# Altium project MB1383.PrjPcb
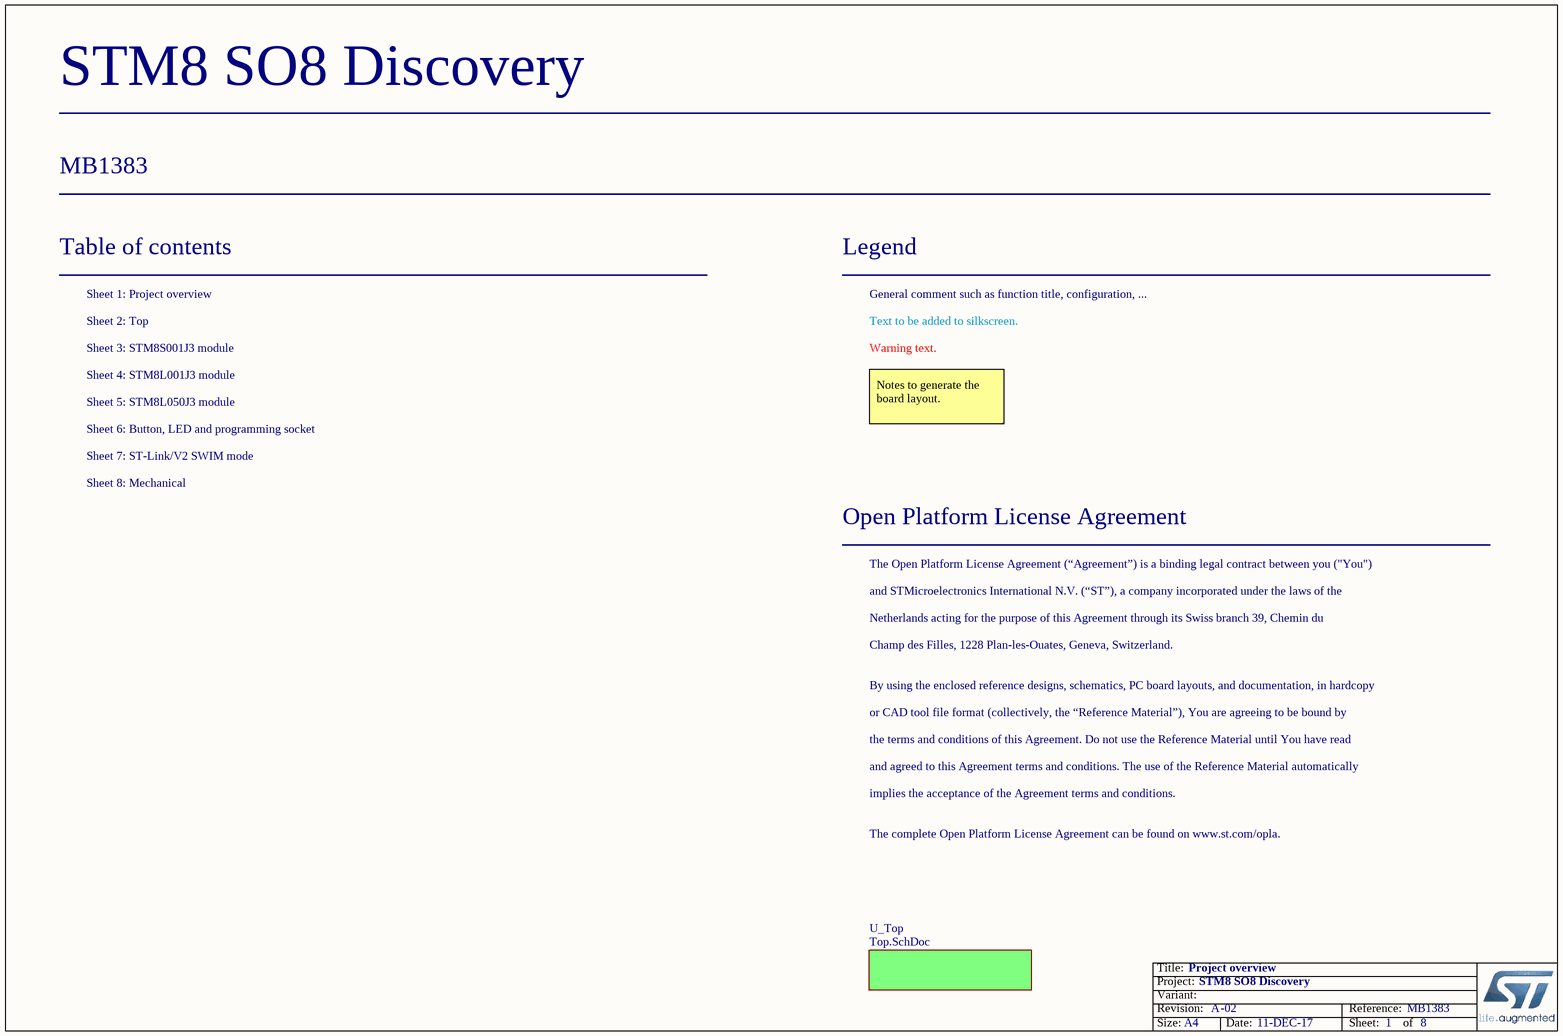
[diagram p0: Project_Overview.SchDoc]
Board_Assembly_Revision: 02; Board_Document_Date: 11-DEC-17; Board_Name: STM8 SO8 Discovery; Board_PCB_Revision: A; Board_Reference: MB1383
8 sheets, 85 parts. Net scope: flat (ports and power ports of the same name join across sheets).
Board file: MB1383.PcbDoc
Sheets:
  Project_Overview.SchDoc
    U_Top = Top.SchDoc
      U_ST-LinkV2_SWIM = ST-LinkV2_SWIM.SchDoc
      U_Mechanical = Mechanical.SchDoc
      U_Button-Led-ProgSocket = Button-Led-ProgSocket.SchDoc
      U_STM8L001J3_Module = STM8L001J3_Module.SchDoc
      U_STM8S001J3_Module = STM8S001J3_Module.SchDoc
      U_STM8L050J3_Module = STM8L050J3_Module.SchDoc

## Sheet Project_Overview.SchDoc: Project overview
size A4; ApprovedBy: Not used; CheckedBy: Not used; Author: Not used; CompanyName: STMicroelectronics; DrawnBy: Not used; Engineer: Not used; Organization: Not used; Address1: Not used; Address2: Not used; Address3: Not used; Address4: Not used; DocumentNumber: MB1134; Revision: Not used; SheetNumber: 1; SheetTotal: 8

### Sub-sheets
U_Top = Top.SchDoc: no entries

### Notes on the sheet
- Table of contents
- Sheet 1: Project overview
- Legend
- General comment such as function title, configuration, ...
- Sheet 2: Top
- Sheet 3: STM8S001J3 module
- Sheet 4: STM8L001J3 module
- Text to be added to silkscreen.
- Warning text.
- Sheet 6: Button, LED and programming socket
- Sheet 5: STM8L050J3 module
- Notes to generate the board layout.
- Sheet 7: ST-Link/V2 SWIM mode
- Sheet 8: Mechanical
- Open Platform License Agreement
- The Open Platform License Agreement (“Agreement”) is a binding legal contract between you ("You")
- and STMicroelectronics International N.V. (“ST”), a company incorporated under the laws of the
- Netherlands acting for the purpose of this Agreement through its Swiss branch 39, Chemin du
- Champ des Filles, 1228 Plan-les-Ouates, Geneva, Switzerland.
- By using the enclosed reference designs, schematics, PC board layouts, and documentation, in hardcopy
- or CAD tool file format (collectively, the “Reference Material”), You are agreeing to be bound by
- the terms and conditions of this Agreement. Do not use the Reference Material until You have read
- and agreed to this Agreement terms and conditions. The use of the Reference Material automatically
- implies the acceptance of the Agreement terms and conditions.
- The complete Open Platform License Agreement can be found on www.st.com/opla.

## Sheet Top.SchDoc: Top
size A4; Date: Not used; ApprovedBy: Not used; CheckedBy: Not used; Author: Not used; CompanyName: STMicroelectronics; DrawnBy: Not used; Engineer: Not used; Organization: Not used; Address1: Not used; Address2: Not used; Address3: Not used; Address4: Not used; DocumentNumber: Not used; Revision: Not used; SheetNumber: 1; SheetTotal: 1
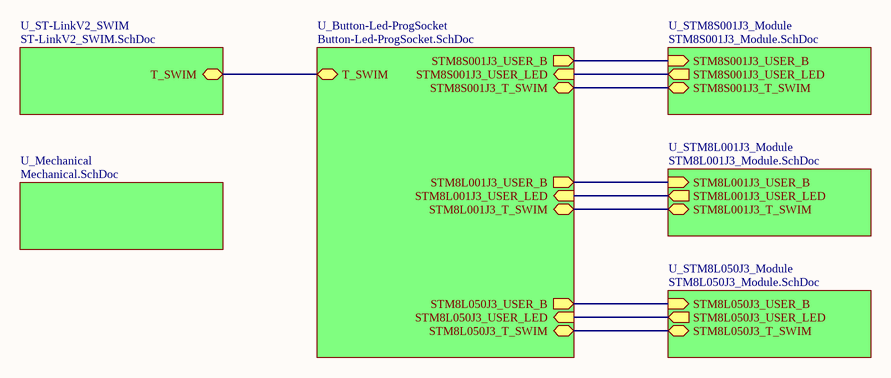
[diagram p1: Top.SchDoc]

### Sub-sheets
U_Button-Led-ProgSocket = Button-Led-ProgSocket.SchDoc: STM8S001J3_USER_B (out), STM8S001J3_USER_LED (in), STM8S001J3_T_SWIM (bidir), STM8L001J3_USER_B (out), STM8L001J3_USER_LED (in), STM8L001J3_T_SWIM (bidir), STM8L050J3_USER_B (out), STM8L050J3_USER_LED (in), STM8L050J3_T_SWIM (bidir), T_SWIM (bidir)
U_Mechanical = Mechanical.SchDoc: no entries
U_ST-LinkV2_SWIM = ST-LinkV2_SWIM.SchDoc: T_SWIM (bidir)
U_STM8L001J3_Module = STM8L001J3_Module.SchDoc: STM8L001J3_USER_B (in), STM8L001J3_USER_LED (out), STM8L001J3_T_SWIM (bidir)
U_STM8L050J3_Module = STM8L050J3_Module.SchDoc: STM8L050J3_USER_B (in), STM8L050J3_USER_LED (out), STM8L050J3_T_SWIM (bidir)
U_STM8S001J3_Module = STM8S001J3_Module.SchDoc: STM8S001J3_USER_B (in), STM8S001J3_USER_LED (out), STM8S001J3_T_SWIM (bidir)

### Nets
(unnamed): sheet U_ST-LinkV2_SWIM/T_SWIM, sheet U_Button-Led-ProgSocket/T_SWIM
(unnamed): sheet U_Button-Led-ProgSocket/STM8S001J3_USER_B, sheet U_STM8S001J3_Module/STM8S001J3_USER_B  [a separate net that carries the same name]
(unnamed): sheet U_Button-Led-ProgSocket/STM8S001J3_USER_LED, sheet U_STM8S001J3_Module/STM8S001J3_USER_LED  [a separate net that carries the same name]
(unnamed): sheet U_Button-Led-ProgSocket/STM8S001J3_T_SWIM, sheet U_STM8S001J3_Module/STM8S001J3_T_SWIM  [a separate net that carries the same name]
(unnamed): sheet U_Button-Led-ProgSocket/STM8L001J3_USER_B, sheet U_STM8L001J3_Module/STM8L001J3_USER_B  [a separate net that carries the same name]
(unnamed): sheet U_Button-Led-ProgSocket/STM8L001J3_USER_LED, sheet U_STM8L001J3_Module/STM8L001J3_USER_LED  [a separate net that carries the same name]
(unnamed): sheet U_Button-Led-ProgSocket/STM8L001J3_T_SWIM, sheet U_STM8L001J3_Module/STM8L001J3_T_SWIM  [a separate net that carries the same name]
(unnamed): sheet U_Button-Led-ProgSocket/STM8L050J3_USER_B, sheet U_STM8L050J3_Module/STM8L050J3_USER_B  [a separate net that carries the same name]
(unnamed): sheet U_Button-Led-ProgSocket/STM8L050J3_USER_LED, sheet U_STM8L050J3_Module/STM8L050J3_USER_LED  [a separate net that carries the same name]
(unnamed): sheet U_Button-Led-ProgSocket/STM8L050J3_T_SWIM, sheet U_STM8L050J3_Module/STM8L050J3_T_SWIM  [a separate net that carries the same name]

## Sheet ST-LinkV2_SWIM.SchDoc: ST-Link/V2 SWIM mode
size A4; Date: Not used; ApprovedBy: Not used; CheckedBy: Not used; Author: Not used; CompanyName: STMicroelectronics; DrawnBy: Not used; Engineer: Not used; Organization: Not used; Address1: Not used; Address2: Not used; Address3: Not used; Address4: Not used; DocumentNumber: Not used; Revision: Not used; SheetNumber: 7; SheetTotal: 8
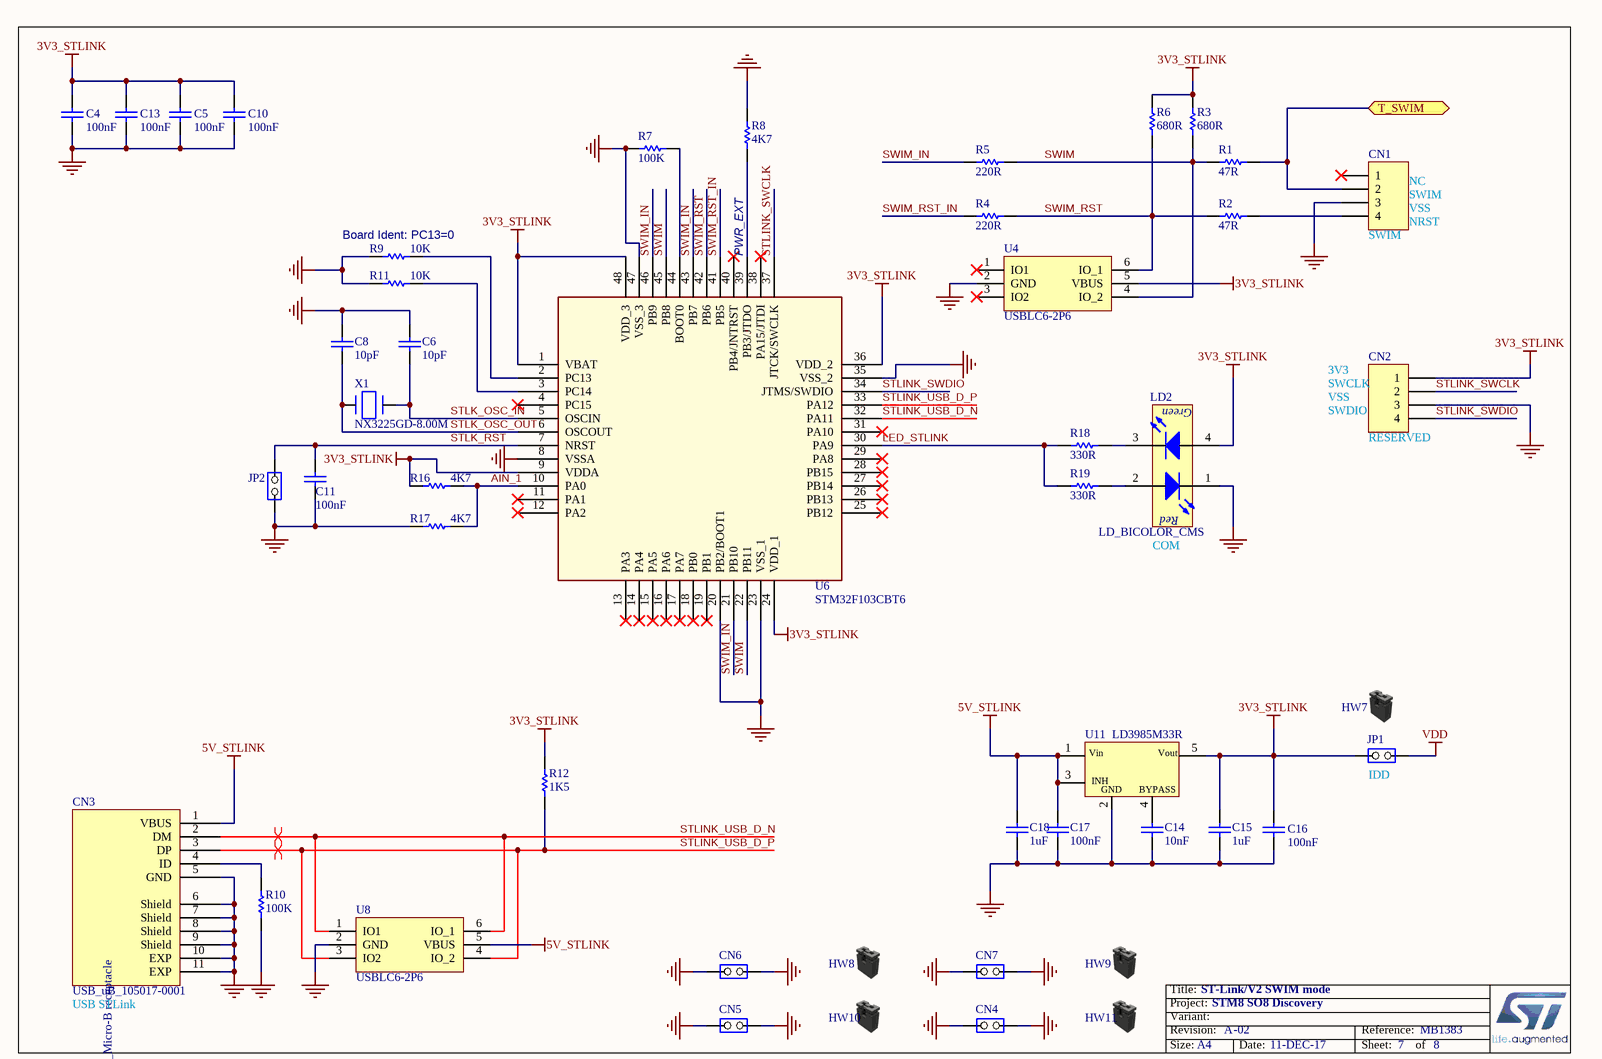
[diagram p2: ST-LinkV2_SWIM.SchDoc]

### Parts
C4  value 100nF  [C0603]  (hidden comment: Capacitor)
C5  value 100nF  [C0603]  (hidden comment: Capacitor)
C6  value 10pF  [C0402]  (hidden comment: Capacitor)
C8  value 10pF  [C0402]  (hidden comment: Capacitor)
C10  value 100nF  [C0603]  (hidden comment: Capacitor)
C11  value 100nF  [C0603]  (hidden comment: Capacitor)
C13  value 100nF  [C0603]  (hidden comment: Capacitor)
C14  value 10nF  [C0603]  (hidden comment: Capacitor)
C15  value 1uF  [C0603]  (hidden comment: Capacitor)
C16  value 100nF  [C0603]  (hidden comment: Capacitor)
C17  value 100nF  [C0603]  (hidden comment: Capacitor)
C18  value 1uF  [C0603]  (hidden comment: Capacitor)
CN1  Header 4  [CON_SAMTEC_TSW-104-07-G-S]  (value not drawn)
CN2  Header 4  [CON_SAMTEC_TSW-104-07-G-S]  (value not drawn)
CN3  value USB_uB_105017-0001  [CON_USBMICROB_MOLEX_105017-0001_H2P90]  (hidden comment: USB_uB_105017.0001)
CN4  Jumper_Header 2x1  [CON_SAMTEC_TSW-102-07-G-S]  (value not drawn)
CN5  Jumper_Header 2x1  [CON_SAMTEC_TSW-102-07-G-S]  (value not drawn)
CN6  Jumper_Header 2x1  [CON_SAMTEC_TSW-102-07-G-S]  (value not drawn)
CN7  Jumper_Header 2x1  [CON_SAMTEC_TSW-102-07-G-S]  (value not drawn)
HW7  Shunt Black 2.54mm  (value not drawn)  (mechanical)
HW8  Shunt Black 2.54mm  (value not drawn)  (mechanical)
HW9  Shunt Black 2.54mm  (value not drawn)  (mechanical)
HW10  Shunt Black 2.54mm  (value not drawn)  (mechanical)
HW11  Shunt Black 2.54mm  (value not drawn)  (mechanical)
JP1  Jumper_Header 2x1  [CON_SAMTEC_TSW-102-07-G-S]  (value not drawn)
JP2  Jumper_Header 2x1  [CON_SAMTEC_TSW-102-07-G-S]  (value not drawn)
LD2  LD_BICOLOR_CMS  [LED_BI-GR_HSMF-A201-A00J1]
R1  value 47R  [R0603]  (hidden comment: Resistor)
R2  value 47R  [R0603]  (hidden comment: Resistor)
R3  value 680R  [R0603]  (hidden comment: Resistor)
R4  value 220R  [R0603]  (hidden comment: Resistor)
R5  value 220R  [R0603]  (hidden comment: Resistor)
R6  value 680R  [R0603]  (hidden comment: Resistor)
R7  value 100K  [R0603]  (hidden comment: Resistor)
R8  value 4K7  [R0603]  (hidden comment: Resistor)
R9  value 10K  [R0603]  (hidden comment: Resistor)
R10  value 100K  [R0603]  (hidden comment: Resistor)
R11  value 10K  [R0603]  (hidden comment: Resistor)
R12  value 1K5  [R0603]  (hidden comment: Resistor)
R16  value 4K7  [R0603]  (hidden comment: Resistor)
R17  value 4K7  [R0603]  (hidden comment: Resistor)
R18  value 330R  [R0402]  (hidden comment: Resistor)
R19  value 330R  [R0402]  (hidden comment: Resistor)
U4  USBLC6-2P6  [ESD_SOT666]
U6  STM32F103CBT6  [ICC_LQFP48_7X7_P050]
U8  USBLC6-2P6  [ESD_SOT666]
U11  LD3985M33R  [REG_SOT23-5L]
X1  value NX3225GD-8.00M  [CRY_NX3225GD_2P]  (hidden comment: XTAL_2_PINS)

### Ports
T_SWIM (bidir)

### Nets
3V3_STLINK: C4.2 C5.2 C10.2 C13.2 C15.2 C16.2 CN2.1 JP1.1(COMMON) LD2.4(YellowGreen_anode) R3.2 R6.2 R12.1 R16.1 U4.5(VBUS) U6.1(VBAT) U6.9(VDDA) U6.24(VDD_1) U6.36(VDD_2) U6.48(VDD_3) U11.5(Vout)
5V_STLINK: C17.2 C18.2 CN3.1(VBUS) U8.5(VBUS) U11.1(Vin) U11.3(CE)
GND: C4.1 C5.1 C6.2 C8.2 C10.1 C11.1 C13.1 C14.1 C15.1 C16.1 C17.1 C18.1 CN1.3 CN2.3 CN3.5(GND) CN3.6(Shield) CN3.7(Shield) CN3.8(Shield) CN3.9(Shield) CN3.10(EXP) CN3.11(EXP) CN4.1(COMMON) CN4.2(NO) CN5.1(COMMON) CN5.2(NO) CN6.1(COMMON) CN6.2(NO) CN7.1(COMMON) CN7.2(NO) JP2.1(COMMON) LD2.1(RED_cathode) R7.1 R8.2 R9.1 R10.1 R11.1 R17.1 U4.2(GND) U6.8(VSSA) U6.20(PB2/BOOT1) U6.23(VSS_1) U6.35(VSS_2) U6.47(VSS_3) U8.2(GND) U11.2(GND)
VDD: JP1.2(NO)
AIN_1: R16.2 R17.2 U6.10(PA0)
LED_STLINK: R18.2 R19.2 U6.30(PA9)
STLINK_SWCLK: CN2.2 U6.37(JTCK/SWCLK)
STLINK_SWDIO: CN2.4 U6.34(JTMS/SWDIO)
STLINK_USB_D_N: CN3.2(DM) U6.32(PA11) U8.1(IO1) U8.6(IO_1)
STLINK_USB_D_P: CN3.3(DP) R12.2 U6.33(PA12) U8.3(IO2) U8.4(IO_2)
STLK_OSC_IN: C6.1 U6.5(OSCIN) X1.2(X2)
STLK_OSC_OUT: C8.1 U6.6(OSCOUT) X1.1(X1)
STLK_RST: C11.2 JP2.2(NO) U6.7(NRST)
SWIM: R1.2 R3.1 R5.1 U4.4(IO_2) U6.22(PB11) U6.45(PB8)
SWIM_IN: R5.2 U6.21(PB10) U6.43(PB7) U6.46(PB9)
SWIM_RST: R2.2 R4.1 R6.1 U4.6(IO_1) U6.42(PB6)
SWIM_RST_IN: R4.2 U6.41(PB5)
T_SWIM: CN1.2 R1.1 ; port T_SWIM
NetC14_2: C14.2 U11.4(BYPASS)
NetCN1_4: CN1.4 R2.1
NetCN3_4: CN3.4(ID) R10.2
NetLD2_2: LD2.2(Red_anode) R19.1
NetLD2_3: LD2.3(YellowGreen_cathode) R18.1
NetR7_2: R7.2 U6.44(BOOT0)
NetR8_1: R8.1 U6.39(PB3/JTDO)
NetR9_2: R9.2 U6.2(PC13)
NetR11_2: R11.2 U6.3(PC14)

Not connected (* = marked no-connect by the designer): CN1 1*; U4 1(IO1)* 3(IO2)*; U6 4(PC15)* 11(PA1)* 12(PA2)* 13(PA3)* 14(PA4)* 15(PA5)* 16(PA6)* 17(PA7)* 18(PB0)* 19(PB1)* 25(PB12)* 26(PB13)* 27(PB14)* 28(PB15)* 29(PA8)* 31(PA10)* 38(PA15/JTDI)* 40(PB4/JNTRST)*

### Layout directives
differential pair: STLINK_USB_D_N, STLINK_USB_D_P

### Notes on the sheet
- (near CN1) SWIM
- (near CN1) NC
- (near R9) Board Ident: PC13=0
- (near U6) PWR_EXT
- (near CN1) VSS
- (near CN1) NRST
- VSS
- (near CN2) SWCLK
- 3V3
- (near CN2) SWDIO
- (near CN2) RESERVED
- COM
- (near JP1) IDD
- USB STLink

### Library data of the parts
C4 C5 C10 C11 C13 C16 C17 = MCD-00211: Capacitor, MLCC, 100nF, 16V, X7R, 10%, 0603, T=0,8mm; Manufacturer_Part_Number: CC0603KRX7R7BB104; Manufacturer: YAGEO; Provided_By: Subcon; Initial_Board_Reference: MB1319
C6 C8 = MCD-00015: Capacitor, MLCC, 10pF, 50V, NPO, 5%, 0402, T=0,5mm; Manufacturer_Part_Number: CC0402JRNPO9BN100; Manufacturer: YAGEO; Provided_By: subcon; Initial_Board_Reference: MB1274
C14 = MCD-00017: Capacitor, MLCC, 10nF, 50V, X7R, 10%, 0603, T=0.8mm; Manufacturer_Part_Number: CC0603KRX7R9BB103; Manufacturer: YAGEO; Provided_By: Subcon; Initial_Board_Reference: MB1274
C15 C18 = MCD-00010: Capacitor, MLCC, 1uF, 16V, X5R, 10%, 0603, T=0,8mm; Manufacturer_Part_Number: CC0603KRX5R7BB105; Manufacturer: YAGEO; Provided_By: Subcon; Initial_Board_Reference: MB1274
CN1 CN2 = Header 4: Header, 4-Pin; Manufacturer: SAMTEC; Manufacturer_Part_Number: TSW-104-07-G-S; Fitted: NO; Provided_By: Subcon
CN3 = MCD-00028: USB-MICRO-B, 0.65mm, RA, SMT, Bottom Mount,; Manufacturer_Part_Number: 1050170001; Manufacturer: MOLEX; Part_Type: Connector; Provided_By: Subcon; Initial_Board_Reference: MB1274
CN4-CN7 JP1 JP2 = MCD-00045: Header, 2x1, 2,54mm, VR, TH, Height 5.84mm/2.54mm; Manufacturer_Part_Number: TSW-102-07-x-S; Manufacturer: SAMTEC; Part_Type: Connector; Value: Shunt not fitted; Provided_By: Subcon; Initial_Board_Reference: MB1274; Remark: 3D KO: BZ: 40098
HW7-HW11 = MCD-00043: SHUNT 2.54mm BLACK; Manufacturer_Part_Number: SNT-100-BK-G; Manufacturer: SAMTEC; Part_Type: Mechanical; Provided_By: Subcon; Initial_Board_Reference: MB1274
LD2 = MCD-00051: LED Bicolor; Manufacturer_Part_Number: HSMF-A201-A00J1; Manufacturer: AVAGO TECHNOLOGIES; Alternate_Manufacturer_Part_Number: LE-RGW35280; Alternate_Manufacturer: EVERLUCK; Part_Type: Display; Provided_By: Subcon; Initial_Board_Reference: MB1274
R1 R2 = MCD-00482: Resistor,47R,0603,1%,1/10W; Manufacturer_Part_Number: RC0603FR-0747RL; Manufacturer: YAGEO; Provided_By: Subcon
R3 R6 = MCD-00508: Resistor,680R,0603,1%,1/10W; Manufacturer_Part_Number: RC0603FR-07680RL; Manufacturer: YAGEO; Provided_By: Subcon
R4 R5 = MCD-00428: Resistor,220R,0603,1%,1/10W; Manufacturer_Part_Number: RC0603FR-07220RL; Manufacturer: YAGEO; Provided_By: Subcon
R7 R10 = MCD-00223: Resistor,100K,0603,1%,1/10W; Manufacturer_Part_Number: RC0603FR-07100KL; Manufacturer: YAGEO; Provided_By: Subcon; Initial_Board_Reference: MB1319
R8 R16 R17 = MCD-00219: Resistor,4K7,0603,1%,1/10W; Manufacturer_Part_Number: RC0603FR-074K7L; Manufacturer: YAGEO; Provided_By: Subcon; Initial_Board_Reference: MB1319
R9 R11 = MCD-00220: Resistor,10K,0603,1%,1/10W; Manufacturer_Part_Number: RC0603FR-0710KL; Manufacturer: YAGEO; Provided_By: Subcon; Initial_Board_Reference: MB1319
R12 = MCD-00217: Resistor,1K5,0603,1%,1/10W; Manufacturer_Part_Number: RC0603FR-071K5L; Manufacturer: YAGEO; Provided_By: Subcon; Initial_Board_Reference: MB1319
R18 R19 = MCD-00062: Resistor,330R,0402,1%,1/16W; Manufacturer_Part_Number: RC0402FR-07330RL; Manufacturer: YAGEO; Provided_By: Subcon; Initial_Board_Reference: MB1274
U4 U8 = MCD-00169: USB OTG FS ESD protection; Manufacturer: STMICROELECTRONICS; Part_Type: IC; Provided_By: Subcon; Initial_Board_Reference: MB1274
U6 = MCD-00085: Medium-density performance line ARM-based 32-bit MCU with 128KB Flash; Manufacturer: STMICROELECTRONICS; Part_Type: IC; Provided_By: Subcon; Initial_Board_Reference: MB1274
U11 = MCD-00086: Ultra low drop-low noise BiCMOS voltage, regulators low ESR capacitors compatible; Manufacturer: STMICROELECTRONICS; Part_Type: IC; Provided_By: Subcon; Initial_Board_Reference: MB1274
X1 = MCD-00092: Crystal 8Mhz, 8pF, -+50PPM, SMD; Manufacturer_Part_Number: NX3225GD 8MHz EXS00A-CG04874; Manufacturer: NDK; Part_Type: Crystal_Osc; Provided_By: STM; Initial_Board_Reference: MB1274

## Sheet Mechanical.SchDoc: Mechanical
size A4; Date: Not used; ApprovedBy: Not used; CheckedBy: Not used; Author: Not used; CompanyName: STMicroelectronics; DrawnBy: Not used; Engineer: Not used; Organization: Not used; Address1: Not used; Address2: Not used; Address3: Not used; Address4: Not used; DocumentNumber: Not used; Revision: Not used; SheetNumber: 8; SheetTotal: 8
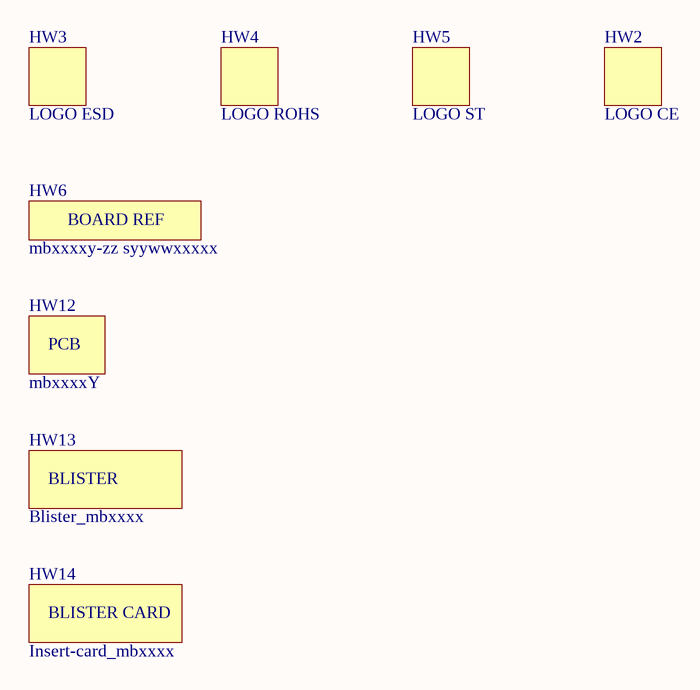
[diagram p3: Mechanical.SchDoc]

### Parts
HW2  value LOGO CE  [LOGO_CE]  (hidden comment: Logo)  (no BOM)
HW3  value LOGO ESD  [LOGO_MAIN_1]  (hidden comment: Logo)  (no BOM)
HW4  value LOGO ROHS  [LOGO_ROHS]  (hidden comment: Logo)  (no BOM)
HW5  value LOGO ST  [LOGO_ST]  (hidden comment: Logo)  (no BOM)
HW6  value mbxxxxy-zz syywwxxxxx  [STICKER_BOARD-REF_25X5]  (hidden comment: STICKER_BOARD_REF)  (mechanical)
HW12  value mbxxxxY  (hidden comment: PCB)  (mechanical)
HW13  value Blister_mbxxxx  (hidden comment: BLISTER)  (mechanical)
HW14  value Insert-card_mbxxxx  (hidden comment: BLISTER CARD)  (mechanical)

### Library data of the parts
HW2 = MCD-00626: CE logo footprint for PCB; Part_Type: Mechanical; Initial_Board_Reference: MB1331
HW3 = MCD-00627: Hand ESD logo footprint for PCB; Part_Type: Mechanical; Initial_Board_Reference: MB1331
HW4 = MCD-00628: ROHS logo footprint for PCB; Part_Type: Mechanical; Initial_Board_Reference: MB1331
HW5 = MCD-00625: STMicroelectronics logo footprint for PCB; Part_Type: Mechanical; Initial_Board_Reference: MB1331
HW6 = MCD-00235: Sticker to mention board reference + serial number; Part_Type: Mechanical; Manufacturer_Part_Number: NA; Provided_By: Subcon; Initial_Board_Reference: MB1319
HW12 = MCD-00216: PCB, xxxx for PCB ref, Y for revision; Part_Type: Mechanical; Provided_By: Subcon; Initial_Board_Reference: MB1319
HW13 = MCD-00037: Part_Type: Mechanical; Provided_By: Subcon; Initial_Board_Reference: MB1274
HW14 = MCD-00038: Part_Type: Mechanical; Provided_By: subcon; Initial_Board_Reference: MB1274

## Sheet Button-Led-ProgSocket.SchDoc: Button, LED and programming socket
size A4; Date: Not used; ApprovedBy: Not used; CheckedBy: Not used; Author: Not used; CompanyName: STMicroelectronics; DrawnBy: Not used; Engineer: Not used; Organization: Not used; Address1: Not used; Address2: Not used; Address3: Not used; Address4: Not used; DocumentNumber: Not used; Revision: Not used; SheetNumber: 6; SheetTotal: 8
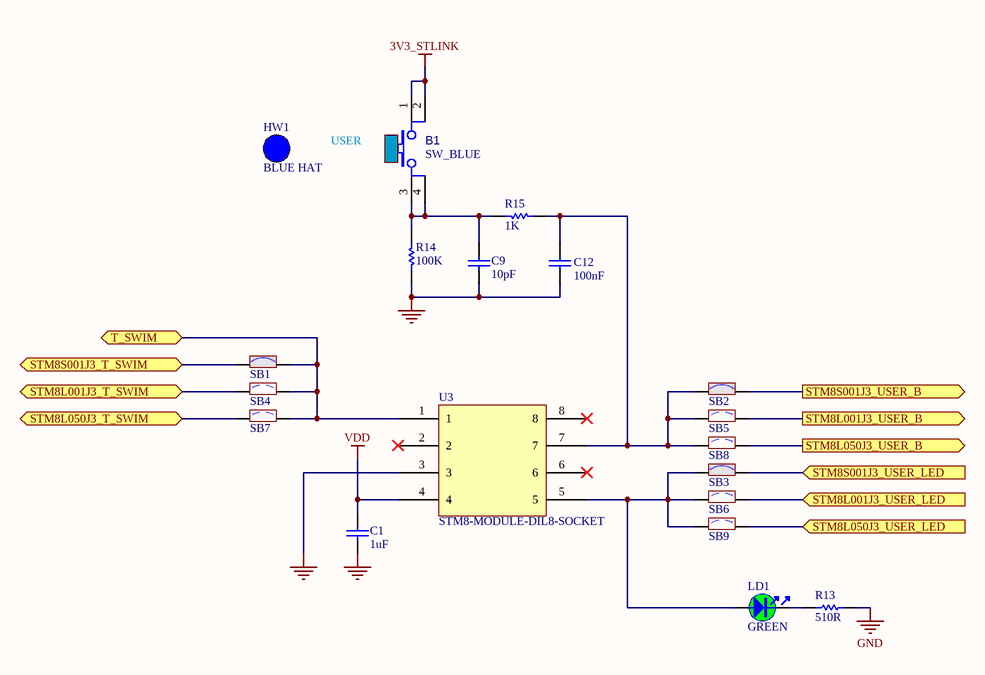
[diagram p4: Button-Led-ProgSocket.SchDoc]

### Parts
B1  value SW_BLUE  [SWI_WEALTHMETAL_TD-0341_4P_BLUE]  (hidden comment: SW-PUSH-CMS_BLUE)
C1  value 1uF  [C0603]  (hidden comment: Capacitor)
C9  value 10pF  [C0402]  (hidden comment: Capacitor)
C12  value 100nF  [C0603]  (hidden comment: Capacitor)
HW1  value BLUE HAT  (hidden comment: BUTTON_HAT_BLUE)  (mechanical)
LD1  value GREEN  [LED_0603_GREEN]  (hidden comment: LED_green)
R13  value 510R  [R0603]  (hidden comment: Resistor)
R14  value 100K  [R0603]  (hidden comment: Resistor)
R15  value 1K  [R0603]  (hidden comment: Resistor)
SB1  SB_ON  [SOLDER-BRIDGE_R0603-0R]  (value not drawn)
SB2  SB_ON  [SOLDER-BRIDGE_R0603-0R]  (value not drawn)
SB3  SB_ON  [SOLDER-BRIDGE_R0603-0R]  (value not drawn)
SB4  SB_OFF  [SOLDER-BRIDGE_R0603-0R]  (value not drawn)
SB5  SB_OFF  [SOLDER-BRIDGE_R0603-0R]  (value not drawn)
SB6  SB_OFF  [SOLDER-BRIDGE_R0603-0R]  (value not drawn)
SB7  SB_OFF  [SOLDER-BRIDGE_R0603-0R]  (value not drawn)
SB8  SB_OFF  [SOLDER-BRIDGE_R0603-0R]  (value not drawn)
SB9  SB_OFF  [SOLDER-BRIDGE_R0603-0R]  (value not drawn)
U3  STM8-MODULE-DIL8-SOCKET  [DIP8]

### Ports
STM8L001J3_T_SWIM (bidir), STM8L001J3_USER_B (out), STM8L001J3_USER_LED (in), STM8L050J3_T_SWIM (bidir), STM8L050J3_USER_B (out), STM8L050J3_USER_LED (in), STM8S001J3_T_SWIM (bidir), STM8S001J3_USER_B (out), STM8S001J3_USER_LED (in), T_SWIM (bidir)

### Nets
3V3_STLINK: B1.1 B1.2
GND: C1.1 C9.1 C12.1 R13.1 R14.1 U3.3
VDD: C1.2 U3.4
STM8L001J3_T_SWIM: SB4.1 ; port STM8L001J3_T_SWIM
STM8L001J3_USER_B: SB5.1 ; port STM8L001J3_USER_B
STM8L001J3_USER_LED: SB6.1 ; port STM8L001J3_USER_LED
STM8L050J3_T_SWIM: SB7.1 ; port STM8L050J3_T_SWIM
STM8L050J3_USER_B: SB8.1 ; port STM8L050J3_USER_B
STM8L050J3_USER_LED: SB9.1 ; port STM8L050J3_USER_LED
STM8S001J3_T_SWIM: SB1.1 ; port STM8S001J3_T_SWIM
STM8S001J3_USER_B: SB2.1 ; port STM8S001J3_USER_B
STM8S001J3_USER_LED: SB3.1 ; port STM8S001J3_USER_LED
T_SWIM: SB1.2 SB4.2 SB7.2 U3.1 ; port T_SWIM
NetB1_3: B1.3 B1.4 C9.2 R14.2 R15.2
NetC12_2: C12.2 R15.1 SB2.2 SB5.2 SB8.2 U3.7
NetLD1_1: LD1.1 SB3.2 SB6.2 SB9.2 U3.5
NetLD1_2: LD1.2 R13.2

Not connected (* = marked no-connect by the designer): U3 2* 6* 8*

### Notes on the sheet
- USER

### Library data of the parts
B1 = MCD-00002: Non-Open Push-Button 0.1A 24V BLUE; Manufacturer_Part_Number: TD0341X-G01-BLU; Manufacturer: WEALTHMETAL; Part_Type: Misc; Provided_By: Subcon; Initial_Board_Reference: MB1274
C1 = MCD-00010: as C15 on sheet ST-LinkV2_SWIM
C9 = MCD-00015: as C6 on sheet ST-LinkV2_SWIM
C12 = MCD-00211: as C4 on sheet ST-LinkV2_SWIM
HW1 = MCD-00634: Blue Hat for switch TD0341X-G01-BLU; Part_Type: Mechanical; Manufacturer_Part_Number: 988.16.09.3.00002_SH-517; Manufacturer: JIUBABA; Provided_By: Subcon; Initial_Board_Reference: MB1319
LD1 = MCD-00050: LED, Green, 0603; Manufacturer_Part_Number: 19-213SYGC/S530-E2/TR8; Manufacturer: EVERLIGHT; Part_Type: Display; Provided_By: Subcon; Initial_Board_Reference: MB1274
R13 = MCD-00225: Resistor,510R,0603,1%,1/10W; Manufacturer_Part_Number: RC0603FR-07510RL; Manufacturer: YAGEO; Provided_By: Subcon; Initial_Board_Reference: MB1319
R14 = MCD-00223: as R7 on sheet ST-LinkV2_SWIM
R15 = MCD-00070: Resistor,1K,0603,1%,1/10W; Manufacturer_Part_Number: RC0603FR-071KL; Manufacturer: YAGEO; Provided_By: Subcon; Initial_Board_Reference: MB1274
SB1-SB3 = MCD-00071: Solder Bridge ON; Part_Type: Mechanical; Provided_By: Subcon; Initial_Board_Reference: MB1274
SB4-SB9 = MCD-00072: Solder Bridge OFF; Part_Type: Mechanical; Initial_Board_Reference: MB1274
U3 = STM8-MODULE-DIL8-SOCKET: STM8-MODULE-DIL8-; Manufacturer: TE CONNECTIVITY / AMP; Manufacturer_Part_Number: 508-AG10D; Provided_By: Subcon; Value: 508-AG10D

## Sheet STM8L001J3_Module.SchDoc: STM8L001J3 module
size A4; Date: Not used; ApprovedBy: Not used; CheckedBy: Not used; Author: Not used; CompanyName: STMicroelectronics; DrawnBy: Not used; Engineer: Not used; Organization: Not used; Address1: Not used; Address2: Not used; Address3: Not used; Address4: Not used; DocumentNumber: Not used; Revision: Not used; SheetNumber: 4; SheetTotal: 8
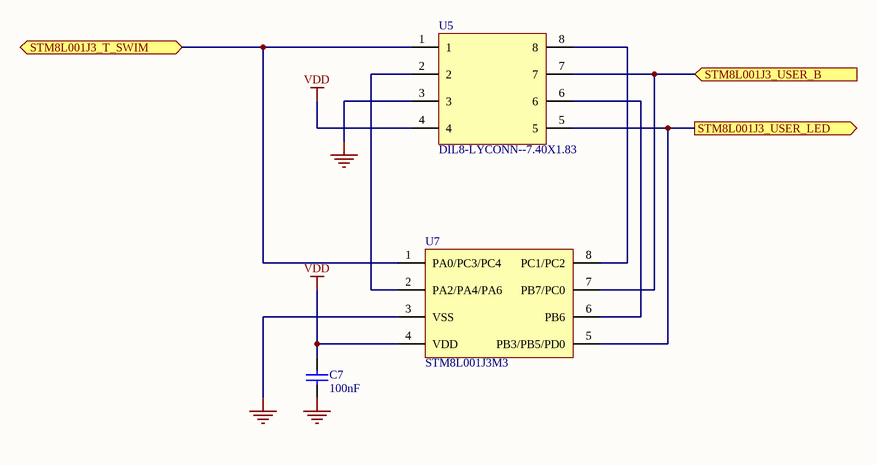
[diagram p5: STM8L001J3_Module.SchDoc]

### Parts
C7  value 100nF  [C0603]  (hidden comment: Capacitor)
U5  value DIL8-LYCONN--7.40X1.83  [CON_LYCONN_DIL8_7P40X1P83_P254]  (hidden comment: DIL8-LYCONN-7.40X1.83)
U7  STM8L001J3M3  [ICC_SO8_5X4_P127]

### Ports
STM8L001J3_T_SWIM (bidir), STM8L001J3_USER_B (in), STM8L001J3_USER_LED (out)

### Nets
GND: C7.1 U5.3 U7.3(VSS)
VDD: C7.2 U5.4 U7.4(VDD)
STM8L001J3_T_SWIM: U5.1 U7.1(PA0/PC3/PC4) ; port STM8L001J3_T_SWIM
STM8L001J3_USER_B: U5.7 U7.7(PB7/PC0) ; port STM8L001J3_USER_B
STM8L001J3_USER_LED: U5.5 U7.5(PB3/PB5/PD0) ; port STM8L001J3_USER_LED
NetU5_2: U5.2 U7.2(PA2/PA4/PA6)
NetU5_6: U5.6 U7.6(PB6)
NetU5_8: U5.8 U7.8(PC1/PC2)

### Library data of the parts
C7 = MCD-00211: as C4 on sheet ST-LinkV2_SWIM
U5 = MCD-01221: PCB socket DIL 8-pin; Part_Type: Connector; Manufacturer: LYCONN; Provided_By: Subcon; Initial_Board_Reference: MB1383
U7 = MCD-01217: STM8L 8-bit ultra-low-power microcontroller, 8-Kbyte Flash; Part_Type: IC; Manufacturer: STMICROELECTRONICS; BMS_Part_Number: 9175272; Provided_By: Subcon; Initial_Board_Reference: MB1383

## Sheet STM8S001J3_Module.SchDoc: STM8S001J3 module
size A4; Date: Not used; ApprovedBy: Not used; CheckedBy: Not used; Author: Not used; CompanyName: STMicroelectronics; DrawnBy: Not used; Engineer: Not used; Organization: Not used; Address1: Not used; Address2: Not used; Address3: Not used; Address4: Not used; DocumentNumber: Not used; Revision: Not used; SheetNumber: 3; SheetTotal: 8
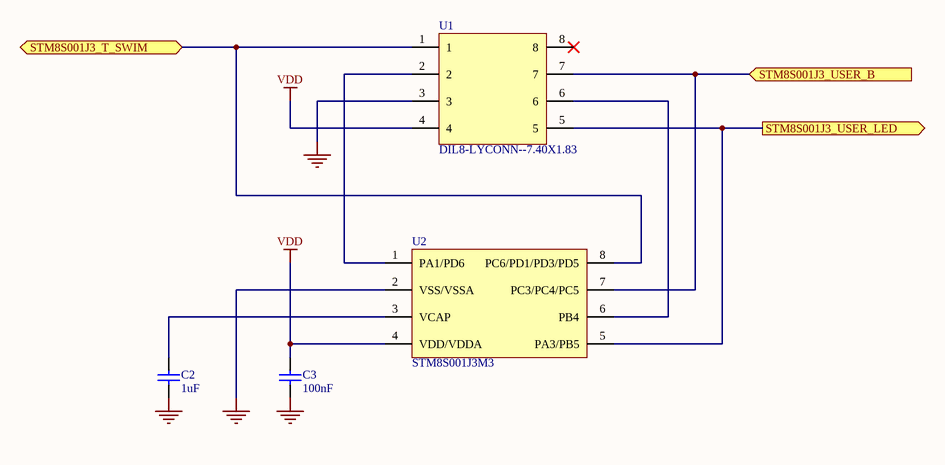
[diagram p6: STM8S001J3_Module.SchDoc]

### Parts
C2  value 1uF  [C0603]  (hidden comment: Capacitor)
C3  value 100nF  [C0603]  (hidden comment: Capacitor)
U1  value DIL8-LYCONN--7.40X1.83  [CON_LYCONN_DIL8_7P40X1P83_P254]  (hidden comment: DIL8-LYCONN-7.40X1.83)
U2  STM8S001J3M3  [ICC_SO8_5X4_P127]

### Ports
STM8S001J3_T_SWIM (bidir), STM8S001J3_USER_B (in), STM8S001J3_USER_LED (out)

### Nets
GND: C2.1 C3.1 U1.3 U2.2(VSS/VSSA)
VDD: C3.2 U1.4 U2.4(VDD/VDDA)
STM8S001J3_T_SWIM: U1.1 U2.8(PC6/PD1/PD3/PD5) ; port STM8S001J3_T_SWIM
STM8S001J3_USER_B: U1.7 U2.7(PC3/PC4/PC5) ; port STM8S001J3_USER_B
STM8S001J3_USER_LED: U1.5 U2.5(PA3/PB5) ; port STM8S001J3_USER_LED
NetC2_2: C2.2 U2.3(VCAP)
NetU1_2: U1.2 U2.1(PA1/PD6)
NetU1_6: U1.6 U2.6(PB4)

Not connected (* = marked no-connect by the designer): U1 8*

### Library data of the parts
C2 = MCD-00010: as C15 on sheet ST-LinkV2_SWIM
C3 = MCD-00211: as C4 on sheet ST-LinkV2_SWIM
U1 = MCD-01221: as U5 on sheet STM8L001J3_Module
U2 = MCD-01218: STM8S 8-bit MCU, 8-Kbyte Flash, 128-byte data EEPROM; Part_Type: IC; Manufacturer: STMICROELECTRONICS; BMS_Part_Number: 9175274; Provided_By: Subcon; Initial_Board_Reference: MB1383

## Sheet STM8L050J3_Module.SchDoc: STM8L050J3 module
size A4; Date: Not used; ApprovedBy: Not used; CheckedBy: Not used; Author: Not used; CompanyName: STMicroelectronics; DrawnBy: Not used; Engineer: Not used; Organization: Not used; Address1: Not used; Address2: Not used; Address3: Not used; Address4: Not used; DocumentNumber: Not used; Revision: Not used; SheetNumber: 5; SheetTotal: 8
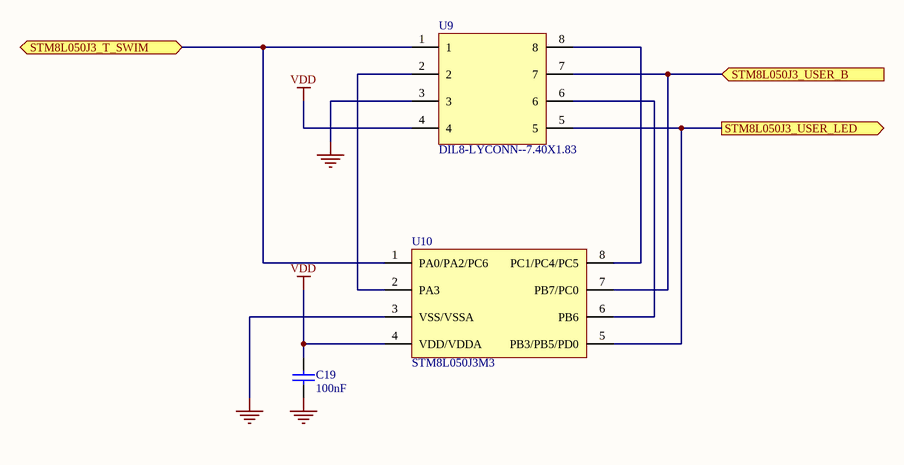
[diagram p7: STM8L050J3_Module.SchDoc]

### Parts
C19  value 100nF  [C0603]  (hidden comment: Capacitor)
U9  value DIL8-LYCONN--7.40X1.83  [CON_LYCONN_DIL8_7P40X1P83_P254]  (hidden comment: DIL8-LYCONN-7.40X1.83)
U10  STM8L050J3M3  [ICC_SO8_5X4_P127]

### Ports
STM8L050J3_T_SWIM (bidir), STM8L050J3_USER_B (in), STM8L050J3_USER_LED (out)

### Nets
GND: C19.1 U9.3 U10.3(VSS/VSSA)
VDD: C19.2 U9.4 U10.4(VDD/VDDA)
STM8L050J3_T_SWIM: U9.1 U10.1(PA0/PA2/PC6) ; port STM8L050J3_T_SWIM
STM8L050J3_USER_B: U9.7 U10.7(PB7/PC0) ; port STM8L050J3_USER_B
STM8L050J3_USER_LED: U9.5 U10.5(PB3/PB5/PD0) ; port STM8L050J3_USER_LED
NetU9_2: U9.2 U10.2(PA3)
NetU9_6: U9.6 U10.6(PB6)
NetU9_8: U9.8 U10.8(PC1/PC4/PC5)

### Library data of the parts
C19 = MCD-00211: as C4 on sheet ST-LinkV2_SWIM
U9 = MCD-01221: as U5 on sheet STM8L001J3_Module
U10 = MCD-01216: STM8L 8-bit ultra-low-power MCU, 8-Kbyte Flash, 256-byte data EEPROM; Part_Type: IC; Manufacturer: STMICROELECTRONICS; BMS_Part_Number: 9175273; Provided_By: Subcon; Initial_Board_Reference: MB1383

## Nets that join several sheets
3V3_STLINK: ST-LinkV2_SWIM (20 pins), Button-Led-ProgSocket (B1.1 B1.2)
GND: ST-LinkV2_SWIM (45 pins), Button-Led-ProgSocket (6 pins), STM8L001J3_Module (C7.1 U5.3 U7.3), STM8S001J3_Module (C2.1 C3.1 U1.3 U2.2), STM8L050J3_Module (C19.1 U9.3 U10.3)
VDD: ST-LinkV2_SWIM (JP1.2), Button-Led-ProgSocket (C1.2 U3.4), STM8L001J3_Module (C7.2 U5.4 U7.4), STM8S001J3_Module (C3.2 U1.4 U2.4), STM8L050J3_Module (C19.2 U9.4 U10.4)
STM8L001J3_T_SWIM: Button-Led-ProgSocket (SB4.1), STM8L001J3_Module (U5.1 U7.1)
STM8L001J3_USER_B: Button-Led-ProgSocket (SB5.1), STM8L001J3_Module (U5.7 U7.7)
STM8L001J3_USER_LED: Button-Led-ProgSocket (SB6.1), STM8L001J3_Module (U5.5 U7.5)
STM8L050J3_T_SWIM: Button-Led-ProgSocket (SB7.1), STM8L050J3_Module (U9.1 U10.1)
STM8L050J3_USER_B: Button-Led-ProgSocket (SB8.1), STM8L050J3_Module (U9.7 U10.7)
STM8L050J3_USER_LED: Button-Led-ProgSocket (SB9.1), STM8L050J3_Module (U9.5 U10.5)
STM8S001J3_T_SWIM: Button-Led-ProgSocket (SB1.1), STM8S001J3_Module (U1.1 U2.8)
STM8S001J3_USER_B: Button-Led-ProgSocket (SB2.1), STM8S001J3_Module (U1.7 U2.7)
STM8S001J3_USER_LED: Button-Led-ProgSocket (SB3.1), STM8S001J3_Module (U1.5 U2.5)
T_SWIM: ST-LinkV2_SWIM (CN1.2 R1.1), Button-Led-ProgSocket (SB1.2 SB4.2 SB7.2 U3.1)

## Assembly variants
DEFAULT: not fitted CN2 JP2 SB4 SB5 SB6 SB7 SB8 SB9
